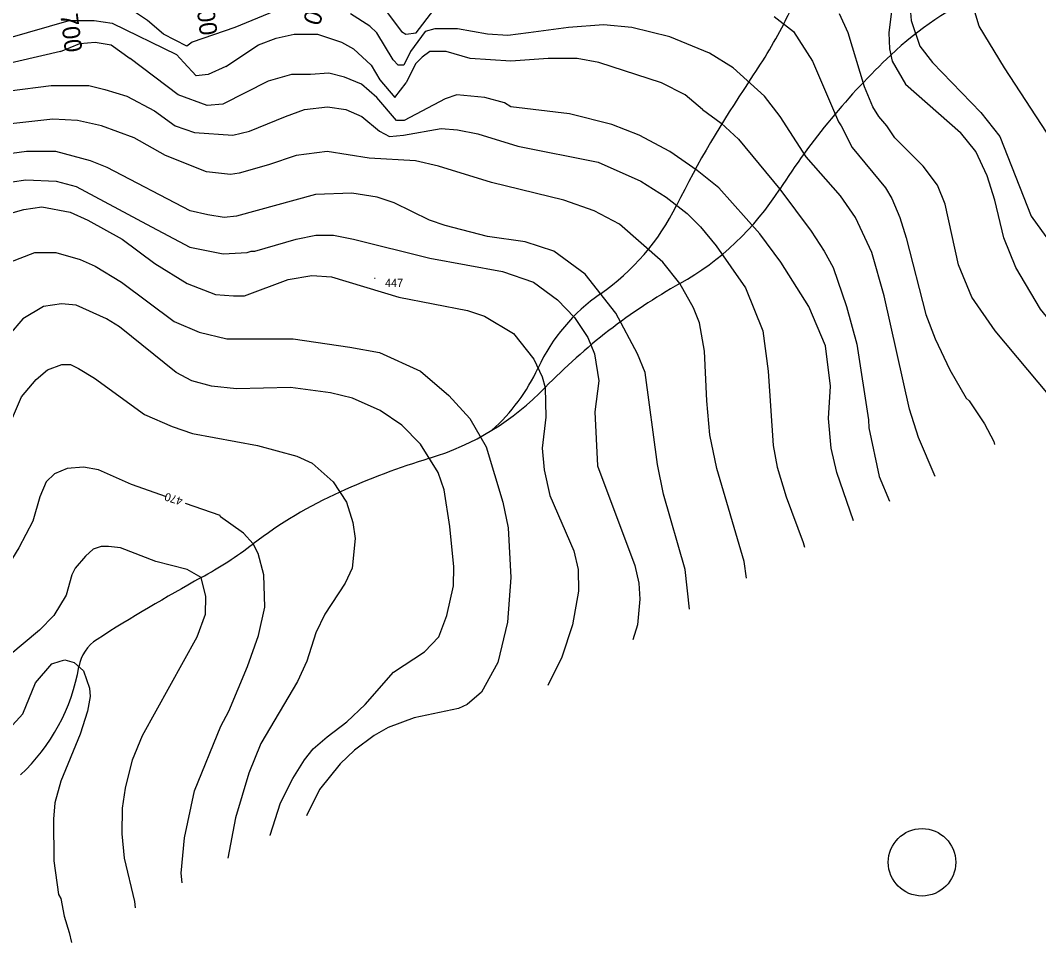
# Model space of a CAD drawing. Extents: x -510989 to -501240, y -1184665 to -1176098.
# Drawn here: x -510018 to -509263, y -1181581 to -1180897 of the extents above; entities that cross this region are included whole.
import ezdxf

# ---------------------------------------------------------------- set-up
doc = ezdxf.new("R2010")
doc.units = 0
for name, color, linetype in [('NAVRH_rozvodnice', 7, 'Continuous'), ('STAV_povodi', 7, 'Continuous'), ('STAV_ryhova_eroze', 7, 'Continuous'), ('trasovani_toku', 7, 'Continuous'), ('vrstevnice_01', 7, 'Continuous'), ('vrstevnice_02', 7, 'Continuous'), ('vrstevnice_04', 7, 'Continuous'), ('vrstevnice_05', 7, 'Continuous')]:
    doc.layers.add(name, color=color, linetype=linetype)

msp = doc.modelspace()

# ---------------------------------------------------------------- linework, layer by layer
at = {"layer": 'NAVRH_rozvodnice'}
for centre, radius, start, end in [((-509618.25, -1180812.49), 187.94, 332.42346, 344.09482), ((-509199.37, -1181105.52), 251.76, 114.32225, 133.36843), ((-509823.31, -1180705.4), 419.29, 325.56382, 332.42346), ((-509009.54, -1181306.48), 528.2, 133.36843, 147.41316), ((-508861.31, -1181364.98), 747.11, 145.56382, 153.7035), ((-509631.57, -1180908.87), 210.05, 299.32731, 327.41316), ((-509686.4, -1180957.26), 173.22, 304.79993, 333.7035), ((-509315.38, -1181471.68), 435.5, 119.32731, 135.9706), ((-509509.01, -1181212.5), 137.61, 124.79993, 155.0724), ((-509763.15, -1181094.38), 142.64, 311.79581, 335.0724), ((-509772.74, -1181029.57), 200.61, 286.91768, 315.9706), ((-509555.13, -1181744.99), 547.17, 106.91768, 114.35133), ((-509644.15, -1181548.32), 331.29, 114.35133, 127.3615), ((-510030.8, -1181041.89), 305.87, 298.77011, 307.3615), ((-509222.49, -1182514.03), 1373.58, 118.77011, 122.51667), ((-509944.7, -1181381.11), 30.05, 122.51667, 170.2119), ((-510115.35, -1181351.67), 143.13, 313.01677, 350.2119)]:
    msp.add_arc(centre, radius, start, end, dxfattribs=at)
at = {"layer": 'STAV_povodi'}
for centre, radius, start, end in [((-509199.37, -1181105.52), 251.76, 114.32225, 133.36843), ((-509009.54, -1181306.48), 528.2, 133.36843, 147.41316), ((-509631.57, -1180908.87), 210.05, 299.32731, 327.41316), ((-509315.38, -1181471.68), 435.5, 119.32731, 135.9706), ((-509772.74, -1181029.57), 200.61, 286.91768, 315.9706), ((-509555.13, -1181744.99), 547.17, 106.91768, 114.35133), ((-509644.15, -1181548.32), 331.29, 114.35133, 127.3615), ((-510030.8, -1181041.89), 305.87, 298.77011, 307.3615), ((-509222.49, -1182514.03), 1373.58, 118.77011, 122.51667), ((-509944.7, -1181381.11), 30.05, 122.51667, 170.2119), ((-510115.35, -1181351.67), 143.13, 313.01677, 350.2119)]:
    msp.add_arc(centre, radius, start, end, dxfattribs=at)
at = {"layer": 'STAV_ryhova_eroze'}
msp.add_circle((-509349.13, -1181521.05), 25, dxfattribs=at)
at = {"layer": 'vrstevnice_01'}
for points in [[(-509252.69, -1180986), (-509288.09, -1180932), (-509306.69, -1180901), (-509323.41, -1180846)], [(-509369.91, -1180876), (-509373.81, -1180906), (-509373.19, -1180918), (-509371.31, -1180927), (-509361.41, -1180944), (-509320.69, -1180980)], [(-509747.19, -1180889), (-509735, -1180905), (-509731.91, -1180907), (-509724.19, -1180906), (-509711.09, -1180889)], [(-509458.81, -1180894), (-509444.5, -1180905), (-509430.31, -1180927), (-509411.09, -1180972)], [(-510036.31, -1180916), (-510027, -1180910), (-509981.5, -1180897), (-509963, -1180897), (-509949.69, -1180899), (-509902, -1180922), (-509896.59, -1180928)], [(-509865.41, -1180931), (-509841.19, -1180915), (-509828, -1180910), (-509814.59, -1180907), (-509797.31, -1180907), (-509779.5, -1180913), (-509770.81, -1180918), (-509757.59, -1180930), (-509751.09, -1180941)], [(-509511.81, -1180963), (-509524.81, -1180952), (-509542.41, -1180943), (-509588.81, -1180928), (-509604.91, -1180925), (-509626.31, -1180925), (-509653.91, -1180927), (-509684.19, -1180925), (-509702, -1180920), (-509714.19, -1180920), (-509719.81, -1180924), (-509724.81, -1180929), (-509731.69, -1180943)], [(-509865.41, -1180931), (-509878.41, -1180937), (-509887.31, -1180938), (-509896.59, -1180928)], [(-510057, -1180953), (-509994.81, -1180945), (-509967, -1180945), (-509955, -1180948), (-509938.81, -1180953), (-509918.31, -1180964), (-509903, -1180975), (-509888.5, -1180980), (-509860.19, -1180982), (-509847.81, -1180979), (-509821, -1180968), (-509807, -1180963), (-509790, -1180961), (-509776.31, -1180963), (-509764.5, -1180968), (-509751.5, -1180979), (-509744.09, -1180983), (-509733.59, -1180982), (-509705.69, -1180977), (-509693.59, -1180978), (-509678.41, -1180981), (-509648.91, -1180990), (-509589.19, -1181002), (-509557.69, -1181016), (-509538.91, -1181028), (-509523.31, -1181040), (-509513.31, -1181050), (-509501.81, -1181064), (-509480.09, -1181095), (-509467.19, -1181127), (-509463.19, -1181157), (-509459.59, -1181212), (-509456.5, -1181228), (-509449.81, -1181250), (-509437.19, -1181284), (-509436.34, -1181287.35)], [(-509751.09, -1180941), (-509740.09, -1180954), (-509731.69, -1180943)], [(-509511.81, -1180963), (-509498.09, -1180973), (-509485.31, -1180985), (-509454.59, -1181022), (-509431.31, -1181053), (-509421.81, -1181068), (-509415.09, -1181080), (-509405.09, -1181109), (-509397.5, -1181137), (-509388.81, -1181193), (-509388.59, -1181199), (-509381, -1181235), (-509373.19, -1181253.28)], [(-509411.09, -1180972), (-509409.09, -1180975), (-509401, -1180991), (-509376.31, -1181021), (-509371.41, -1181029), (-509365.5, -1181043), (-509361, -1181058), (-509346.31, -1181115), (-509339.5, -1181133), (-509328.5, -1181156), (-509316.5, -1181177), (-509314.09, -1181179), (-509302.91, -1181196), (-509296, -1181209), (-509295.27, -1181211.24)], [(-509210.93, -1181165.74), (-509251.41, -1181123), (-509261.19, -1181111), (-509279.5, -1181080), (-509288.41, -1181058), (-509295.09, -1181030), (-509300.81, -1181012), (-509309.31, -1180994), (-509320.69, -1180980)], [(-509521.52, -1181333.31), (-509524.69, -1181304), (-509540.81, -1181248), (-509545.31, -1181226), (-509554.41, -1181158), (-509560.09, -1181144), (-509576.09, -1181114), (-509599, -1181085), (-509622.09, -1181068), (-509643.5, -1181061), (-509671.31, -1181057), (-509702.81, -1181049), (-509714.31, -1181045), (-509740.5, -1181032), (-509753.19, -1181028), (-509771.81, -1181025), (-509798.91, -1181026), (-509857.41, -1181042), (-509866.69, -1181043), (-509878.81, -1181041), (-509891.91, -1181038), (-509953.31, -1181006), (-509965.81, -1181001), (-509991.5, -1180994), (-510013.09, -1180994), (-510035.09, -1180997)], [(-510032.81, -1181042), (-510015.09, -1181037), (-510001.69, -1181035), (-509980.81, -1181039), (-509967.59, -1181045), (-509942.31, -1181059), (-509917.91, -1181077), (-509893.91, -1181092), (-509872.91, -1181100), (-509859.69, -1181101), (-509851.5, -1181101), (-509819.19, -1181089), (-509801.59, -1181086), (-509787.09, -1181087), (-509737, -1181102), (-509686.09, -1181112), (-509673.5, -1181116), (-509652, -1181129), (-509636.91, -1181148), (-509630.69, -1181161), (-509628.5, -1181169), (-509628, -1181191), (-509630.81, -1181214), (-509629.31, -1181230), (-509625.19, -1181249), (-509607.19, -1181290), (-509604, -1181304), (-509603.91, -1181320), (-509608.41, -1181345), (-509616.19, -1181369), (-509626.54, -1181389.97)], [(-509832.53, -1181501.11), (-509832.5, -1181501), (-509824.81, -1181477), (-509815.59, -1181459), (-509806.91, -1181445), (-509800.69, -1181437), (-509790.19, -1181428), (-509775.69, -1181417), (-509762, -1181404), (-509741.09, -1181380), (-509718.09, -1181365), (-509707.5, -1181354), (-509701.5, -1181338), (-509696.59, -1181316), (-509696.41, -1181302), (-509699.31, -1181272), (-509703.41, -1181245), (-509707.81, -1181232), (-509720.91, -1181211), (-509734.81, -1181197), (-509751, -1181186), (-509771.5, -1181177), (-509787.69, -1181173), (-509817.41, -1181169), (-509857.5, -1181170), (-509875.91, -1181168), (-509890.5, -1181164), (-509902.09, -1181158), (-509944.09, -1181124), (-509953.91, -1181118), (-509976.31, -1181108), (-509987.31, -1181107), (-510000.5, -1181109), (-510015.91, -1181118), (-510026.09, -1181130)], [(-509909.43, -1181250.06), (-509935.41, -1181241), (-509959.81, -1181230), (-509970.81, -1181228), (-509983, -1181229), (-509992.31, -1181233), (-509998.59, -1181239), (-510003.19, -1181250), (-510008.41, -1181268), (-510018.81, -1181288), (-510026.31, -1181300), (-510040.69, -1181317)], [(-509897.83, -1181536.34), (-509898.5, -1181529), (-509896, -1181503), (-509888.69, -1181468), (-509869, -1181420), (-509863.09, -1181409), (-509849.41, -1181376), (-509841.09, -1181353), (-509836.41, -1181332), (-509837.09, -1181308), (-509841.5, -1181292), (-509845.19, -1181285), (-509852.31, -1181277), (-509869.19, -1181265), (-509869.5, -1181264), (-509895.37, -1181254.97)], [(-510026.09, -1181422), (-510015.81, -1181411), (-510006.5, -1181388), (-509994.41, -1181374), (-509988.09, -1181372), (-509984.81, -1181371), (-509977.81, -1181373), (-509970.81, -1181379), (-509966.41, -1181392), (-509966, -1181398), (-509967.81, -1181409), (-509973.31, -1181426), (-509987.59, -1181461), (-509992.09, -1181477), (-509993.19, -1181489), (-509993, -1181520), (-509989.31, -1181545), (-509987.81, -1181548), (-509985.31, -1181561), (-509981.59, -1181573), (-509979.9, -1181580.61)]]:
    msp.add_lwpolyline(points, dxfattribs=at)
at = {"layer": 'vrstevnice_02'}
for points in [[(-509829.19, -1180890), (-509858.59, -1180902), (-509890.31, -1180913), (-509894.31, -1180916), (-509911.5, -1180907), (-509923.5, -1180897), (-509938.19, -1180887)], [(-509358.19, -1180885), (-509357.19, -1180897), (-509350.81, -1180916), (-509341.31, -1180928)], [(-509454.41, -1180968), (-509465.91, -1180953), (-509489.09, -1180932), (-509506.81, -1180921), (-509536.19, -1180909), (-509564.19, -1180902), (-509585.19, -1180900), (-509611.19, -1180902), (-509641, -1180906), (-509656.31, -1180908), (-509671.41, -1180907), (-509693.5, -1180903), (-509710.31, -1180903), (-509717.59, -1180905), (-509728.5, -1180920), (-509733.41, -1180930), (-509737.5, -1180930), (-509741.31, -1180926), (-509753.41, -1180906), (-509758.5, -1180901), (-509772.81, -1180892)], [(-509375.31, -1180975), (-509381.19, -1180968), (-509385.69, -1180961), (-509391.69, -1180946), (-509403.81, -1180906), (-509410.31, -1180892)], [(-509988, -1180920), (-510070.19, -1180939), (-510125.81, -1180947), (-510138.69, -1180950), (-510156.91, -1180959), (-510170.91, -1180971), (-510178, -1180979), (-510181.5, -1180981), (-510191.69, -1180999), (-510200.59, -1181004), (-510204.59, -1180999), (-510206.5, -1180992), (-510207, -1180978), (-510200.69, -1180953), (-510176.19, -1180903)], [(-509988, -1180920), (-509973.5, -1180914), (-509962.31, -1180913), (-509950.5, -1180915), (-509936.31, -1180925)], [(-509802.69, -1180937), (-509816.69, -1180937), (-509834, -1180942), (-509867.59, -1180959), (-509879.09, -1180960), (-509900.81, -1180952), (-509936.31, -1180925)], [(-509341.31, -1180928), (-509305.59, -1180965), (-509291.5, -1180983)], [(-509777.41, -1180939), (-509789.09, -1180936), (-509802.69, -1180937)], [(-509400, -1181267.75), (-509412.31, -1181232), (-509416.5, -1181214), (-509418.59, -1181192), (-509417.09, -1181168), (-509420.81, -1181138), (-509433, -1181109), (-509453.81, -1181076), (-509469.5, -1181055), (-509499.91, -1181021), (-509515.81, -1181008), (-509536.19, -1180994), (-509558.81, -1180982), (-509579.09, -1180974), (-509610.59, -1180966), (-509654, -1180961), (-509658.81, -1180958), (-509673.41, -1180954), (-509694.09, -1180952), (-509702.81, -1180955), (-509733, -1180971), (-509738.81, -1180971), (-509753.41, -1180954), (-509764.81, -1180944), (-509777.41, -1180939)], [(-509479.21, -1181310.48), (-509480.91, -1181298), (-509501.31, -1181229), (-509506.41, -1181204), (-509508.69, -1181179), (-509510.31, -1181142), (-509514.09, -1181121), (-509518.5, -1181110), (-509528.69, -1181092), (-509541.31, -1181076), (-509573.5, -1181048), (-509592.19, -1181038), (-509614.69, -1181030), (-509668.31, -1181017), (-509707.69, -1181005), (-509724.81, -1181001), (-509759.09, -1180999), (-509790.19, -1180994), (-509813.31, -1180997), (-509833.69, -1181004), (-509855.59, -1181010), (-509861.81, -1181011), (-509879.59, -1181009), (-509910, -1180997), (-509933.31, -1180984), (-509957.5, -1180975), (-509975.41, -1180971), (-509993.59, -1180970), (-510047.31, -1180976)], [(-509339.37, -1181235.03), (-509351.81, -1181206), (-509358.31, -1181185), (-509377.19, -1181101), (-509386.31, -1181069), (-509398.41, -1181043), (-509409.59, -1181027), (-509435, -1180998), (-509454.41, -1180968)], [(-509246.54, -1181184.95), (-509294.91, -1181127), (-509312.31, -1181102), (-509322.19, -1181078), (-509331.91, -1181033), (-509337.69, -1181019), (-509348.31, -1181005), (-509369.41, -1180984), (-509375.31, -1180975)], [(-509291.5, -1180983), (-509268.19, -1181042), (-509257.41, -1181057), (-509249.69, -1181066), (-509233.19, -1181080), (-509195.19, -1181107), (-509170.59, -1181126), (-509159.01, -1181137.73)], [(-510034.09, -1181018), (-510013.59, -1181015), (-509991.09, -1181016), (-509976.31, -1181020), (-509924.19, -1181048), (-509892, -1181065), (-509867.31, -1181070), (-509849.59, -1181069), (-509846.69, -1181068), (-509843.81, -1181068), (-509813.31, -1181059), (-509798.69, -1181056), (-509785.59, -1181056), (-509770.59, -1181059), (-509714.09, -1181073), (-509660.09, -1181083), (-509637.31, -1181091), (-509619.5, -1181104), (-509606.81, -1181117), (-509597, -1181132), (-509592, -1181144), (-509588.69, -1181164), (-509591.81, -1181187), (-509589.81, -1181227), (-509562.19, -1181301), (-509559.19, -1181314), (-509558.41, -1181326), (-509560.19, -1181345), (-509563.6, -1181356.01)], [(-510025.5, -1181076), (-510007.09, -1181069), (-509991.31, -1181069), (-509973.41, -1181074), (-509962.19, -1181079), (-509942.69, -1181091), (-509903.69, -1181120), (-509885.19, -1181128), (-509864.69, -1181133), (-509815.31, -1181133), (-509773.31, -1181139), (-509751.5, -1181143), (-509721.09, -1181157), (-509700.09, -1181175), (-509684.31, -1181192), (-509672.41, -1181213), (-509660, -1181254), (-509656.09, -1181273), (-509654, -1181310), (-509656.41, -1181343), (-509663.69, -1181373), (-509675.69, -1181395), (-509686.41, -1181404), (-509692.81, -1181407), (-509725.59, -1181414), (-509744.91, -1181421), (-509755.31, -1181427), (-509769.91, -1181438), (-509780.5, -1181448), (-509796, -1181467), (-509805.56, -1181486.56)], [(-510049.19, -1181251), (-510016.91, -1181176), (-510006, -1181163), (-509997.69, -1181156), (-509986.91, -1181152), (-509980.59, -1181152), (-509974.5, -1181155), (-509962.81, -1181162), (-509925.69, -1181189), (-509905.19, -1181198), (-509890.19, -1181203), (-509841.81, -1181212), (-509812.81, -1181220), (-509801.41, -1181225), (-509785.69, -1181239), (-509775.81, -1181254), (-509771.09, -1181269), (-509769.41, -1181281), (-509771.59, -1181303), (-509776.81, -1181314), (-509792, -1181337), (-509798.69, -1181351), (-509805.31, -1181372), (-509812.19, -1181387), (-509839.31, -1181433), (-509848.31, -1181455), (-509858.09, -1181488), (-509863.75, -1181517.95)], [(-509932.24, -1181554.9), (-509932.91, -1181550), (-509940.41, -1181518), (-509942.19, -1181500), (-509941.91, -1181481), (-509939.69, -1181466), (-509934.59, -1181445), (-509927.19, -1181427), (-509886.69, -1181354), (-509880.5, -1181337), (-509880.09, -1181324), (-509883.59, -1181310), (-509893.91, -1181304), (-509917.19, -1181298), (-509943.41, -1181288), (-509952.31, -1181287), (-509957.69, -1181287), (-509963.81, -1181289), (-509969.31, -1181294), (-509977, -1181303), (-509979.5, -1181308), (-509983.81, -1181323), (-509992.81, -1181338), (-510003.41, -1181349), (-510026.19, -1181368)]]:
    msp.add_lwpolyline(points, dxfattribs=at)

# ---------------------------------------------------------------- texts
at = {"layer": 'trasovani_toku'}
for s, rotation, p in [('0,600', 277.34932, (-509889.91, -1180865.46)), ('0,500', 251.57228, (-509794.63, -1180856.1)), ('0,700', 277.30272, (-509990.05, -1180878.01))]:
    msp.add_text(s, height=13, rotation=rotation, dxfattribs=at).set_placement(p)
at = {"layer": 'vrstevnice_04'}
msp.add_text('470', height=6, rotation=162.44798, dxfattribs=at).set_placement((-509896.82, -1181250.87))
at = {"layer": 'vrstevnice_05'}
for s, p in [('.', (-509755.96, -1181088.56)), ('447', (-509747.29, -1181094.44))]:
    msp.add_text(s, height=6, dxfattribs=at).set_placement(p)

doc.saveas('drawing.dxf')
